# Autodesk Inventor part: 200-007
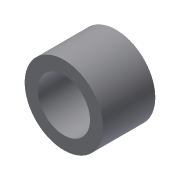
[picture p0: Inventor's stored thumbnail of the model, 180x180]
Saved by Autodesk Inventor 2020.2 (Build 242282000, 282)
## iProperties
Created: 2014-01
Part Number: 200-007
Material: Ogólny
Document SubType Name: Modeling
Designer: F.Stasiak
Density: 1 g/cm^3
Appearance: Domyślna
Manager: www.cadconsulting.pl
Company: Fabian Stasiak CAD Consulting
Author: F.Stasiak
Subject: Zbiór ćwiczeń. Autodesk Inventor 2020. Kurs podstawowy
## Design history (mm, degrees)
sketch "Szkic1"
  geometry: C1 r 15 at (0, 0); C2 r 10 at (0, 0); 1 further point
  constraints: 2 centre point, 2 coincident
  dimensions: "d0" = 30 diameter of C1; "d1" = 20 diameter of C2
extrude "Wyciągnięcie proste1" new body sketch "Szkic1" distance "d2" = 20; taper "d3" = 0 deg
node "Bryła1"
